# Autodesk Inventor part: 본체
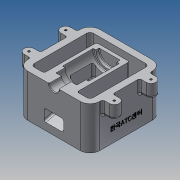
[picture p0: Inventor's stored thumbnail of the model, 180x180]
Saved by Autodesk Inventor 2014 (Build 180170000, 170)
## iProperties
Created: 2018-01
Part Number: 본체
Material: 알루미늄 6061
Document SubType Name: Modeling
Designer: 601-26
Density: 2.71 g/cm^3
Appearance: 알루미늄 - 평지
Mass: 998.37 g
Surface Area: 834.76 cm^2
Volume: 368.402 cm^3
Author: 601-26
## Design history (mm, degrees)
sketch "스케치1"
  geometry: L1 (55, -55)-(-55, -55); L2 (-55, -55)-(-55, 55); L3 (-55, 55)-(55, 55); L4 (55, 55)-(55, -55); L5 (55, -55)-(-55, 55); L6 (-55, -55)-(55, 55); 1 further point
  constraints: 12 end point, 2 midpoint, 2 parallel, 1 horizontal, 1 perpendicular
  dimensions: "d0" = 110 distance of L1.start L1.end; "d1" = 110 distance of L3.end L1.start
extrude "돌출1" new body sketch "스케치1" distance "d2" = 65; taper "d3" = 0 deg
sketch "스케치2"
  geometry: L1 (-55, -55)-(55, -55) reference; L2 (55, -55)-(55, 55) reference; L3 (55, 55)-(-55, 55) reference; L4 (-55, 55)-(-55, -55) reference; L5 (-45, 55)-(-45, 45); L6 (-55, 45)-(-45, 45); L7 (-55, 0)-(55, 0); L8 (-55, 25)-(-45, 25); L9 (-55, -25)-(-45, -25); L10 (45, 45)-(55, 45); L11 (-55, -45)-(-45, -45); L12 (45, -45)-(55, -45); L13 (45, 25)-(55, 25); L14 (45, -25)-(55, -25); L15 (-45, 25)-(35, 25); L16 (-45, 45)-(45, 45); L17 (-45, -25)-(35, -25); L18 (-45, -45)-(45, -45); L19 (55, 45)-(55, -45); L20 (-45, 45)-(-45, 25); L21 (-45, -45)-(-45, -55); L22 (-45, -25)-(-45, -45); L23 (-45, 25)-(-45, -25); L24 (35, 55)-(35, 45); L25 (35, 45)-(35, 25); L26 (35, -45)-(35, -55); L27 (35, 25)-(45, 25); L28 (35, -25)-(45, -25); L29 (35, 25)-(35, -25); L30 (35, -25)-(35, -45); L31 (45, 45)-(45, -45); 1 further point
  constraints: 54 end point, 16 perpendicular, 14 point on line, 9 parallel, 2 midpoint, 1 collinear, 1 other
  dimensions: "d4" = 10 distance between parallel lines of L4 L5; "d5" = 10 distance between parallel lines of L6 L3; "d6" = 50 distance between parallel lines of L9 L8; "d8" = 10 distance between parallel lines of L1 L11; "d9" = 20 distance between parallel lines of L19 L24; "d10" = 10 distance between parallel lines of L2 L31
extrude "돌출2" cut sketch "스케치2" distance "d11" = 110; taper "d12" = 0 deg
sketch "스케치4"
  geometry: L1 (-45, -25)-(35, -25) reference; L2 (35, -25)-(35, 25) reference; L3 (-55, 55)-(-55, -55) reference; L4 (35, 0)-(-55, 0); L5 (30, 0)-(30, -16); L6 (25, 0)-(25, -20); L7 (35, -20)-(25, -20); L8 (-22, 0)-(-22, -16); L9 (35, -16)-(30, -16); L10 (-36, -20)-(-36, -16); L11 (-55, -7.5)-(-36, -7.5); L12 (-36, -16)-(-55, -16); L13 (-36, -16)-(-36, 0); L14 (-22, -16)-(-22, -20); L15 (-22, -20)-(-55, -20); L16 (25, -16)-(-22, -16); L17 (-22, -16)-(-36, -16); L18 (25, -20)-(-22, -20); L19 (30, -16)-(30, -20); L20 (30, -16)-(25, -16); 1 further point
  constraints: 34 end point, 14 perpendicular, 14 point on line, 4 parallel, 3 midpoint
  dimensions: "d13" = 5 distance between parallel lines of L2 L5; "d14" = 5 distance between parallel lines of L6 L5; "d15" = 40 diameter of L7 L4; "d16" = 47 distance between parallel lines of L6 L8; "d17" = 32 diameter of L9 L4; "d18" = 14 distance between parallel lines of L8 L10; "d19" = 15 diameter of L11 L4
revolve "회전1" sketch "스케치4" stored, may be unused: angle "d20" = 90 deg
sketch "스케치8"
  geometry: L1 (80, -65)-(0, -65) reference; L2 (0, 0)-(80, 0) reference; L3 (0, 0)-(0, -65) reference; L4 (-10, -65)-(-10, 0) reference; L5 (-10, -35)-(90.247, -35); L6 (80, 0)-(80, -65); L7 (-10, -65)-(100, -65) reference; L8 (100, -65)-(100, 0) reference; L9 (80, 0)-(80, -65) reference; L10 (80, -35)-(0, -56.436); 1 further point
  constraints: 6 end point, 6 point on line, 2 perpendicular
  dimensions: "d44" = 30 distance between parallel lines of L1 L5; "d45" = 20 distance between parallel lines of L8 L6; "d46" = 105 deg angle of L3 L10
extrude "돌출4" cut sketch "스케치8" stored distance "d47" = 30; taper "d48" = 0 deg
sketch "스케치10"
  geometry: L1 (-25, 65)-(22, 65) reference; L2 (-25, 65)-(-25, 65) reference; L3 (22, 65)-(-25, 65) reference; L4 (22, 65)-(22, 65) reference; L5 (-35, 30)-(45, 8.564) reference; L6 (45, 65)-(45, 8.564) reference; L7 (-35, 65)-(45, 65) reference; L8 (-35, 65)-(-35, 30) reference; L9 (55, 11.061)-(-20, 31.157); L10 (55, 0)-(55, 65) reference; L11 (55, 29.061)-(17, 39.243); L12 (22, 45)-(-25, 45) reference; L13 (17, 54.243)-(-20, 54.243); L14 (17, 54.243)-(17, 39.243); L15 (-20, 54.243)-(-20, 31.157); 3 further points
  constraints: 10 end point, 2 midpoint, 2 parallel, 2 point on line, 1 perpendicular, 1 vertical alignment
  dimensions: "d55" = 5 distance between parallel lines of L5 L9; "d56" = 18 distance of L9.start L11.start; "d57" = 75 deg angle of L10 L11; "d58" = 105 deg angle of L10 L9 (derived); "d59" = 37 distance of L13.start L13.end; "d60" = 15 distance of L13.start L11.end
extrude "돌출5" cut sketch "스케치10" stored distance "d61" = 30; taper "d62" = 0 deg
sketch "스케치11"
  geometry: L1 (55, 55)-(-55, 55) reference; L2 (-55, 55)-(-55, 7.5) reference; L3 (35, 25)-(-45, 25) reference; L4 (55, 65)-(-55, 65); L5 (-28, 55)-(-28, 75); L6 (-20.5, 65)-(-20.5, 55); L7 (-35.5, 65)-(-35.5, 55); L8 (-55, 55)-(55, 55) reference; L9 (-35.5, 55)-(-20.5, 55); A1 r 7.5 centre (-28, 65) between (-20.5, 65) and (-35.5, 65); 1 further point
  constraints: 10 end point, 6 point on line, 3 perpendicular, 2 point on circle, 2 tangent, 1 centre point, 1 collinear, 1 midpoint, 1 parallel
  dimensions: "d66" = 10 distance between parallel lines of L1 L4; "d67" = 27 distance between parallel lines of L2 L5; "d68" = 15 diameter of A1
extrude "돌출6" join sketch "스케치11" distance "d69" = 20; taper "d70" = 0 deg
sketch "스케치12"
  geometry: A1 r 7.5 centre (-28, 65) between (-20.5, 65) and (-35.5, 65) reference; 2 further points
  constraints: 1 coincident
hole "구멍1" sketch "스케치12" at (-28, 65) diameter "d71" = 3.242; stored, may be unused: countersink angle "d75" = 82 deg, drill point angle "d77" = 118 deg; dims "d72" = 9, "d73" = 3.023, "d74" = 2, "d76" = 11
fillet "모깎기1" dims "d78" = 15
sketch "스케치13"
  geometry: L1 (-34.5, 0)-(-34.5, -65) reference; 2 further points
  constraints: 1 other
  dimensions: "d79" = 20 distance of point (20.5, -65) point (20.5, -45); "d80" = 55 distance from line of L1 point (20.5, -45)
extrude "돌출7" join sketch "스케치13" distance "d81" = 0.5; taper "d82" = 0 deg
fillet "모깎기2" dims "d83" = 1
fillet "모깎기3" dims "d84" = 3
fillet "모깎기4" dims "d85" = 3
fillet "모깎기5" dims "d86" = 3
fillet "모깎기6" dims "d87" = 3
fillet "모깎기7" dims "d88" = 3
chamfer "모따기1" distance "d89" = 1; stored, may be unused: second distance "d90" = 2, angle "d91" = 45 deg
fillet "모깎기9" dims "d93" = 5
fillet "모깎기10" dims "d94" = 3
node "솔리드1"
mirror "대칭1"
mirror "대칭2"
mirror "대칭3"
mirror "대칭4"
node "투영된 루프11"
node "투영된 루프12"
